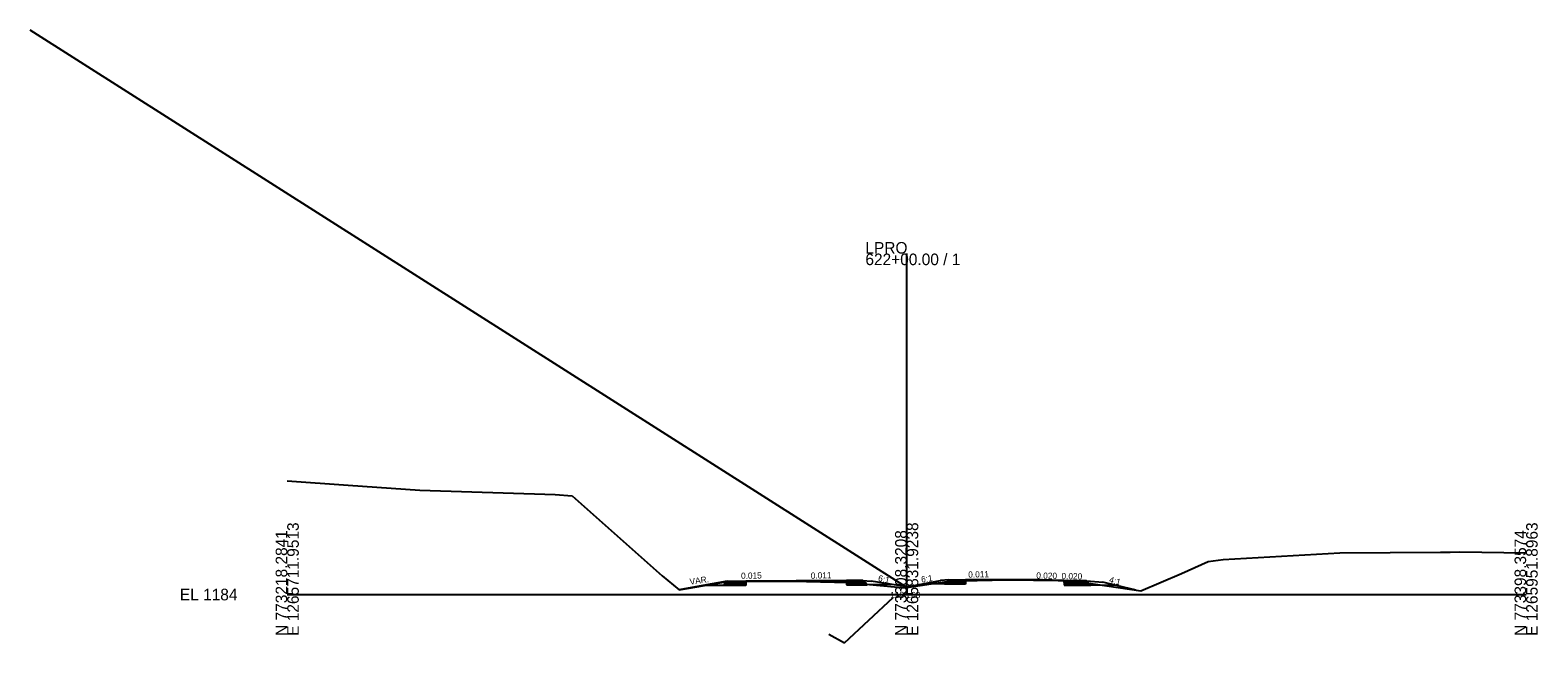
# Model space of a CAD drawing. Extents: x -3833 to 1267678, y -522 to 773248.
# Drawn here: x 2937.8 to 3302.8, y 2988.3 to 3136.7 of the extents above; entities that cross this region are included whole.
import ezdxf

# ---------------------------------------------------------------- set-up
doc = ezdxf.new("R2010")
doc.units = 0
for name, color, linetype in [('Exist Cross Section Cell', 7, 'Continuous'), ('Exist XS Center Line Elevation Label', 7, 'Continuous'), ('Exist XS Ground Line', 7, 'Continuous'), ('Prop CMT DNC', 7, 'Continuous'), ('Prop CMT Pvmt Course 1', 7, 'Continuous'), ('Prop CMT Shld Paved Course 1', 7, 'Continuous'), ('Prop CMT Shld Paved Course 2', 7, 'Continuous'), ('Prop CMT Shld Paved Course 4', 7, 'Continuous'), ('Prop CMT Slope Grass', 7, 'Continuous'), ('Prop CMT Subgrade Earthwork', 7, 'Continuous'), ('Prop Corridor Mesh Bottom', 7, 'Continuous'), ('Prop XS Ditch Slope Text', 7, 'Continuous'), ('Prop XS Finish Grade', 7, 'Continuous'), ('Prop XS SE Text', 7, 'Continuous'), ('Scratch_Level_1', 7, 'Continuous'), ('Scratch_Level_5', 7, 'Continuous')]:
    doc.layers.add(name, color=color, linetype=linetype)

msp = doc.modelspace()

# ---------------------------------------------------------------- linework, layer by layer
at = {"layer": 'Exist Cross Section Cell'}
for p, q in [((3150, 3000), (3150, 3082.61)), ((3000, 3000), (3150, 3000)), ((3150, 3000), (3300, 3000))]:
    msp.add_line(p, q, dxfattribs=at)
at = {"layer": 'Exist XS Ground Line'}
for p, q in [((3000, 3027.54), (3014.78, 3026.51)), ((3014.78, 3026.51), (3032.14, 3025.26)), ((3032.14, 3025.26), (3064.86, 3024.26)), ((3064.86, 3024.26), (3069, 3023.94)), ((3069, 3023.94), (3090.76, 3004.58)), ((3223.04, 3008.01), (3226.68, 3008.5)), ((3226.68, 3008.5), (3254.9, 3010.1)), ((3254.9, 3010.1), (3279.3, 3010.3)), ((3279.3, 3010.3), (3281.61, 3010.29)), ((3281.61, 3010.29), (3283.86, 3010.35)), ((3283.86, 3010.35), (3300, 3010.08)), ((3206.67, 3000.88), (3216.54, 3005.12)), ((3216.54, 3005.12), (3223.04, 3008.01)), ((3090.76, 3004.58), (3094.91, 3001.15)), ((3094.91, 3001.15), (3097.37, 3001.55)), ((3097.37, 3001.55), (3106.16, 3003.06)), ((3106.16, 3003.06), (3107.26, 3003.11)), ((3107.26, 3003.11), (3111.13, 3003.25)), ((3111.13, 3003.25), (3113.69, 3003.26)), ((3113.69, 3003.26), (3122.38, 3003.25)), ((3122.38, 3003.25), (3132.54, 3002.98)), ((3132.54, 3002.98), (3135.49, 3002.91)), ((3135.49, 3002.91), (3136.08, 3002.87)), ((3136.08, 3002.87), (3138.21, 3002.78)), ((3138.21, 3002.78), (3140.99, 3002.42)), ((3140.99, 3002.42), (3149.62, 3001.62)), ((3149.62, 3001.62), (3150, 3001.68)), ((3150, 3001.68), (3159.19, 3003.08)), ((3159.19, 3003.08), (3159.86, 3003.2)), ((3159.86, 3003.2), (3163.57, 3003.36)), ((3163.57, 3003.36), (3174.1, 3003.58)), ((3174.1, 3003.58), (3174.77, 3003.6)), ((3174.77, 3003.6), (3186.65, 3003.44)), ((3186.65, 3003.44), (3187.39, 3003.43)), ((3187.39, 3003.43), (3191.63, 3003.19)), ((3191.63, 3003.19), (3192.98, 3002.96)), ((3192.98, 3002.96), (3206.67, 3000.88))]:
    msp.add_line(p, q, dxfattribs=at)
at = {"layer": 'Prop CMT Pvmt Course 1'}
for p, q in [((3111.05, 3003.28), (3123.24, 3003.45)), ((3111.06, 3003.25), (3111.05, 3003.28)), ((3111.06, 3003.25), (3111.05, 3003.25)), ((3111.79, 3003.26), (3111.06, 3003.25)), ((3115.46, 3003.27), (3111.79, 3003.26)), ((3122.09, 3003.28), (3115.46, 3003.27)), ((3123.24, 3003.26), (3122.09, 3003.28)), ((3123.24, 3003.45), (3123.24, 3003.45)), ((3123.24, 3003.45), (3135.42, 3003.41)), ((3123.98, 3003.24), (3123.24, 3003.26)), ((3123.24, 3003.26), (3123.24, 3003.26)), ((3135.42, 3003.16), (3123.98, 3003.24)), ((3135.42, 3003.41), (3135.42, 3003.41)), ((3135.42, 3003.41), (3135.42, 3003.16)), ((3135.42, 3003.16), (3135.42, 3003.16)), ((3135.42, 3003.16), (3135.42, 3003.16)), ((3176.16, 3003.59), (3164.22, 3003.56)), ((3164.22, 3003.56), (3164.22, 3003.56)), ((3164.22, 3003.56), (3164.22, 3003.31)), ((3164.22, 3003.38), (3165.62, 3003.42)), ((3164.22, 3003.31), (3164.22, 3003.38)), ((3164.22, 3003.31), (3164.22, 3003.31)), ((3165.62, 3003.42), (3170.7, 3003.53)), ((3170.7, 3003.53), (3174.46, 3003.6)), ((3174.46, 3003.6), (3176.18, 3003.59)), ((3182.38, 3003.57), (3176.16, 3003.59)), ((3176.16, 3003.59), (3176.16, 3003.59)), ((3176.18, 3003.59), (3176.28, 3003.58)), ((3176.28, 3003.58), (3176.4, 3003.58)), ((3176.4, 3003.58), (3182.48, 3003.54)), ((3188.11, 3003.4), (3182.38, 3003.57)), ((3182.48, 3003.54), (3188.1, 3003.4)), ((3188.1, 3003.4), (3188.11, 3003.1)), ((3188.11, 3003.1), (3188.11, 3003.4))]:
    msp.add_line(p, q, dxfattribs=at)
at = {"layer": 'Prop CMT Shld Paved Course 1'}
for p, q in [((3106.31, 3003.01), (3106.55, 3003.26)), ((3111.05, 3003.03), (3106.31, 3003.01)), ((3106.55, 3003.26), (3111.05, 3003.28)), ((3111.05, 3003.28), (3111.05, 3003.03)), ((3139.42, 3003.43), (3135.42, 3003.41)), ((3135.42, 3003.41), (3135.42, 3003.16)), ((3135.42, 3003.16), (3139.67, 3003.19)), ((3135.42, 3003.16), (3135.42, 3003.16)), ((3139.67, 3003.19), (3139.42, 3003.43)), ((3139.42, 3003.43), (3139.42, 3003.43)), ((3139.67, 3003.19), (3139.67, 3003.19)), ((3139.67, 3003.19), (3139.67, 3003.19)), ((3159.97, 3003.34), (3160.22, 3003.59)), ((3164.22, 3003.31), (3159.97, 3003.34)), ((3160.22, 3003.59), (3164.22, 3003.56)), ((3164.22, 3003.56), (3164.22, 3003.31)), ((3188.11, 3003.35), (3188.11, 3003.1)), ((3193.53, 3003.3), (3188.11, 3003.35)), ((3188.11, 3003.1), (3193.78, 3003.05)), ((3193.78, 3003.05), (3193.53, 3003.3))]:
    msp.add_line(p, q, dxfattribs=at)
at = {"layer": 'Prop CMT Shld Paved Course 2'}
for p, q in [((3105.99, 3002.67), (3106.31, 3003.01)), ((3111.05, 3002.7), (3105.99, 3002.67)), ((3106.31, 3003.01), (3110.62, 3003.03)), ((3111.05, 3003.03), (3111.05, 3002.7)), ((3139.67, 3003.19), (3135.42, 3003.16)), ((3135.42, 3003.16), (3135.42, 3002.83)), ((3135.42, 3002.83), (3140, 3002.85)), ((3135.42, 3002.83), (3135.42, 3002.83)), ((3140, 3002.85), (3139.67, 3003.19)), ((3139.67, 3003.19), (3139.67, 3003.19)), ((3140, 3002.85), (3140, 3002.85)), ((3140, 3002.85), (3140, 3002.85)), ((3159.64, 3003.01), (3159.97, 3003.34)), ((3164.22, 3002.97), (3159.64, 3003.01)), ((3159.97, 3003.34), (3164.22, 3003.31)), ((3164.22, 3003.31), (3164.22, 3002.97)), ((3188.11, 3003.1), (3188.11, 3002.77)), ((3193.78, 3003.05), (3188.11, 3003.1)), ((3188.11, 3002.77), (3194.12, 3002.71)), ((3194.12, 3002.71), (3193.78, 3003.05))]:
    msp.add_line(p, q, dxfattribs=at)
at = {"layer": 'Prop CMT Shld Paved Course 4'}
for p, q in [((3105.55, 3002.21), (3105.99, 3002.67)), ((3111.06, 3002.24), (3105.55, 3002.21)), ((3105.99, 3002.67), (3106.49, 3002.68)), ((3106.49, 3002.68), (3111.05, 3002.7)), ((3111.05, 3002.7), (3111.06, 3002.24)), ((3139.5, 3002.85), (3135.42, 3002.83)), ((3135.42, 3002.83), (3135.42, 3002.37)), ((3135.42, 3002.37), (3140.46, 3002.4)), ((3135.42, 3002.37), (3135.42, 3002.37)), ((3140, 3002.85), (3139.5, 3002.85)), ((3139.5, 3002.85), (3139.5, 3002.85)), ((3140.46, 3002.4), (3140, 3002.85)), ((3140, 3002.85), (3140, 3002.85)), ((3140.46, 3002.4), (3140.46, 3002.4)), ((3140.46, 3002.4), (3140.46, 3002.4)), ((3159.18, 3002.56), (3159.64, 3003.01)), ((3164.22, 3002.51), (3159.18, 3002.56)), ((3159.64, 3003.01), (3160.14, 3003.01)), ((3160.14, 3003.01), (3164.22, 3002.97)), ((3164.22, 3002.97), (3164.22, 3002.51)), ((3188.11, 3002.77), (3188.11, 3002.31)), ((3193.62, 3002.72), (3188.11, 3002.77)), ((3188.11, 3002.31), (3194.58, 3002.25)), ((3194.12, 3002.71), (3193.62, 3002.72)), ((3194.58, 3002.25), (3194.12, 3002.71))]:
    msp.add_line(p, q, dxfattribs=at)
at = {"layer": 'Prop CMT Slope Grass'}
for p, q in [((3106.55, 3003.26), (3100.61, 3002.18)), ((3139.42, 3003.43), (3141.42, 3003.27)), ((3146.49, 3002.43), (3141.42, 3003.27)), ((3153.93, 3002.6), (3158.22, 3003.43)), ((3160.22, 3003.59), (3158.22, 3003.43)), ((3193.53, 3003.3), (3197.53, 3002.98)), ((3200.78, 3002.2), (3197.53, 3002.98))]:
    msp.add_line(p, q, dxfattribs=at)
at = {"layer": 'Prop CMT Subgrade Earthwork'}
for p, q in [((3111.06, 3002.24), (3100.61, 3002.18)), ((3111.05, 3003.25), (3111.06, 3002.24)), ((3135.42, 3002.91), (3135.42, 3002.37)), ((3146.49, 3002.43), (3135.42, 3002.37)), ((3164.22, 3002.51), (3153.93, 3002.6)), ((3164.21, 3003.38), (3164.22, 3002.51)), ((3188.09, 3003.39), (3188.11, 3002.31)), ((3200.78, 3002.2), (3188.11, 3002.31))]:
    msp.add_line(p, q, dxfattribs=at)
at = {"layer": 'Prop Corridor Mesh Bottom'}
for p, q in [((3111.05, 3003.28), (3111.05, 3003.03)), ((3135.42, 3003.41), (3135.42, 3003.16)), ((3164.22, 3003.56), (3164.22, 3003.31)), ((3188.11, 3003.35), (3188.11, 3003.1))]:
    msp.add_line(p, q, dxfattribs=at)
at = {"layer": 'Prop XS Finish Grade'}
for p, q in [((3100.61, 3002.18), (3094.91, 3001.15)), ((3150, 3001.85), (3146.49, 3002.43)), ((3150, 3001.85), (3153.93, 3002.6)), ((3205.57, 3001.04), (3200.78, 3002.2))]:
    msp.add_line(p, q, dxfattribs=at)
at = {"layer": 'Scratch_Level_1'}
msp.add_line((3150, 3001.68), (2937.75, 3136.74), dxfattribs=at)
at = {"layer": 'Scratch_Level_5'}
for p, q in [((3134.92, 2988.3), (3146.77, 2999.33)), ((3131.13, 2990.41), (3134.92, 2988.3))]:
    msp.add_line(p, q, dxfattribs=at)

# ---------------------------------------------------------------- texts
at = {"layer": 'Exist Cross Section Cell'}
for s, p in [('LPRO', (3140, 3082.61)), ('622+00.00 / 1', (3140, 3079.81)), ('EL 1184', (2974, 2998.6))]:
    msp.add_text(s, height=2.8, dxfattribs=at).set_placement(p)
for s, p in [('E 1265711.9513', (3002.8, 2990)), ('E 1265831.9238', (3152.8, 2990)), ('E 1265951.8963', (3302.8, 2990)), ('N 773218.2841', (3000, 2990)), ('N 773308.3208', (3150, 2990)), ('N 773398.3574', (3300, 2990))]:
    msp.add_text(s, height=2.8, rotation=90, dxfattribs=at).set_placement(p)
at = {"layer": 'Exist XS Center Line Elevation Label'}
msp.add_text('1185.68', height=1.5, dxfattribs=at).set_placement((3146.04, 2999.16))
at = {"layer": 'Prop CMT DNC'}
for p in [(3106.15, 3003.06), (3106.55, 3003.26), (3106.55, 3003.26), (3111.05, 3003.28), (3111.05, 3003.28), (3123.24, 3003.45), (3135.42, 3003.41), (3135.42, 3003.41), (3139.42, 3003.43), (3141.42, 3003.27), (3158.22, 3003.43), (3160.22, 3003.59), (3164.22, 3003.56), (3164.22, 3003.56), (3176.16, 3003.59), (3188.11, 3003.35), (3188.11, 3003.35)]:
    msp.add_text('X', height=0.00025, dxfattribs=at).set_placement(p)
at = {"layer": 'Prop XS Ditch Slope Text'}
for s, rotation, p in [('6:1', 346.8183, (3142.97, 3003.31)), ('6:1', 8.224, (3153.61, 3002.9)), ('VAR.', 8.224, (3097.56, 3002.36)), ('4:1', 344.5428, (3198.91, 3002.97))]:
    msp.add_text(s, height=1.5, rotation=rotation, dxfattribs=at).set_placement(p)
at = {"layer": 'Prop XS SE Text'}
for s, rotation, p in [('0.015', 1.397, (3109.91, 3003.79)), ('0.011', 1.299, (3126.79, 3003.84)), ('0.011', 1.2955, (3164.93, 3004.1)), ('0.020', 358.8542, (3181.38, 3003.88)), ('0.020', 358.8542, (3187.48, 3003.76))]:
    msp.add_text(s, height=1.5, rotation=rotation, dxfattribs=at).set_placement(p)

doc.saveas('drawing.dxf')
